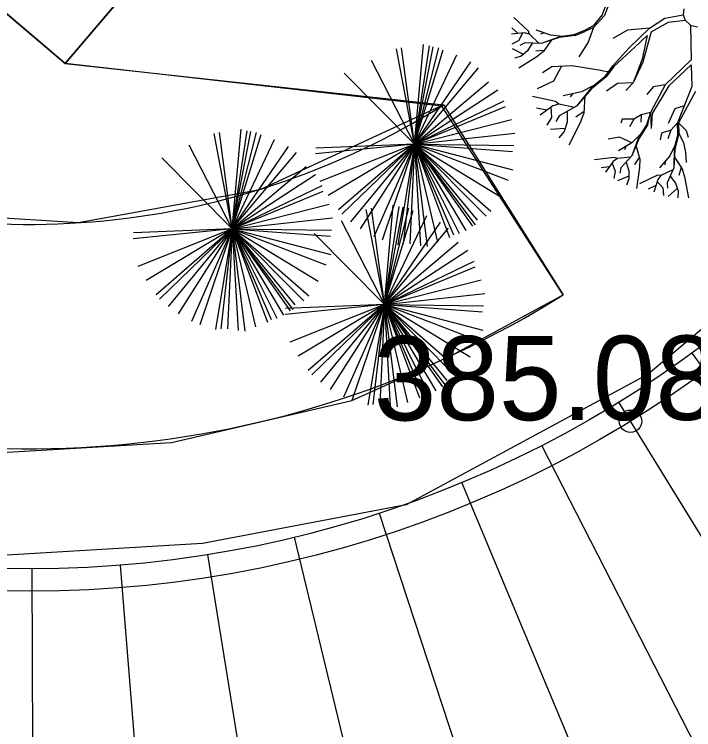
# Model space of a CAD drawing. Extents: x -438303 to -437792, y -1133191 to -1132731.
# Drawn here: x -438058.05 to -438052, y -1132962.9 to -1132956.53 of the extents above; entities that cross this region are included whole.
import ezdxf

# ---------------------------------------------------------------- set-up
doc = ezdxf.new("R2010")
doc.units = 0
for name, color, linetype in [('NADPRAZI', 7, 'Continuous'), ('OSY', 7, 'Continuous'), ('SILNA 1', 7, 'Continuous'), ('Vrstva 1', 7, 'Continuous'), ('Vrstva 3', 7, 'Continuous'), ('Vrstva 40', 7, 'Continuous')]:
    doc.layers.add(name, color=color, linetype=linetype)

# ---------------------------------------------------------------- blocks, each defined once
blk = doc.blocks.new('A$C6C6266F8')
at = {"layer": 'OSY'}
for p, q in [((38.268, -92.388), (74.623, -180.157)), ((60.258, -185.456), (30.902, -95.106)), ((-45.522, -189.612), (-23.345, -97.237)), ((45.522, -189.612), (23.345, -97.237)), ((-30.505, -192.599), (-15.643, -98.769)), ((30.505, -192.599), (15.643, -98.769)), ((-15.3, -194.399), (-7.846, -99.692)), ((0, -195), (0, -100)), ((7.846, -99.692), (15.3, -194.399))]:
    blk.add_line(p, q, dxfattribs=at)

msp = doc.modelspace()

# ---------------------------------------------------------------- linework, layer by layer
at = {"layer": 'DEFPOINTS'}
msp.add_circle((-438057.9113, -1132951.4681), 10.2, dxfattribs=at)
msp.add_circle((-438057.9113, -1132951.4681), 10.2, dxfattribs=at)
at = {"layer": 'NADPRAZI'}
msp.add_circle((-438057.9113, -1132951.4681), 10, dxfattribs=at)
msp.add_circle((-438057.9113, -1132951.4681), 10, dxfattribs=at)
msp.add_circle((-438057.9113, -1132951.4681), 10, dxfattribs=at)
msp.add_circle((-438057.9113, -1132951.4681), 10, dxfattribs=at)
msp.add_circle((-438057.9113, -1132951.4681), 10, dxfattribs=at)
at = {"layer": 'SILNA 1'}
msp.add_circle((-438052.5625, -1132960.1531), 0.1, dxfattribs=at)
msp.add_circle((-438052.5625, -1132960.1531), 0.1, dxfattribs=at)
msp.add_circle((-438052.5625, -1132960.1531), 0.1, dxfattribs=at)
msp.add_circle((-438052.5625, -1132960.1531), 0.1, dxfattribs=at)
at = {"layer": 'Vrstva 1'}
for p, q in [((-438052.4146, -1132950.8696), (-438057.5966, -1132956.9644)), ((-438057.5966, -1132956.9644), (-438063.6914, -1132951.7824)), ((-438052.7262, -1132956.3612), (-438052.7949, -1132956.5367)), ((-438052.7595, -1132956.3777), (-438052.8134, -1132956.5318)), ((-438052.0875, -1132956.4789), (-438052.0924, -1132956.5311)), ((-438053.4718, -1132956.676), (-438053.6008, -1132956.5553)), ((-438052.8134, -1132956.5318), (-438052.8958, -1132956.6303)), ((-438052.7949, -1132956.5367), (-438052.8915, -1132956.6429)), ((-438052.3944, -1132956.6509), (-438052.2565, -1132956.5601)), ((-438052.2565, -1132956.5601), (-438052.0924, -1132956.5311)), ((-438052.0924, -1132956.5311), (-438052.0764, -1132956.578)), ((-438052.3781, -1132956.6813), (-438052.2237, -1132956.5977)), ((-438052.2237, -1132956.5977), (-438052.0764, -1132956.578)), ((-438052.0764, -1132956.578), (-438052.0288, -1132956.6232)), ((-438052.0288, -1132956.6232), (-438052.0213, -1132956.933)), ((-438052.0288, -1132956.6232), (-438051.9657, -1132956.6376)), ((-438053.5626, -1132956.6973), (-438053.6182, -1132956.6459)), ((-438053.4618, -1132956.7044), (-438053.4718, -1132956.676)), ((-438053.2705, -1132956.7136), (-438053.4028, -1132956.6679)), ((-438052.9724, -1132956.6698), (-438053.0654, -1132956.7093)), ((-438053.0558, -1132956.7159), (-438052.9687, -1132956.6787)), ((-438052.8958, -1132956.6303), (-438052.9724, -1132956.6698)), ((-438052.8915, -1132956.6429), (-438052.9687, -1132956.6787)), ((-438052.8915, -1132956.6429), (-438052.9398, -1132956.7748)), ((-438052.5899, -1132956.6665), (-438052.7199, -1132956.7427)), ((-438052.3944, -1132956.6509), (-438052.5899, -1132956.6665)), ((-438052.5731, -1132956.826), (-438052.3944, -1132956.6509)), ((-438052.3781, -1132956.6813), (-438052.451, -1132956.9539)), ((-438053.5054, -1132956.6919), (-438053.6227, -1132956.703)), ((-438053.5239, -1132956.6949), (-438053.5591, -1132956.7623)), ((-438053.4618, -1132956.7044), (-438053.5054, -1132956.6919)), ((-438053.3761, -1132956.7861), (-438053.4618, -1132956.7044)), ((-438053.3314, -1132956.6929), (-438053.3624, -1132956.7022)), ((-438053.1909, -1132956.726), (-438053.3586, -1132956.7868)), ((-438053.1975, -1132956.7343), (-438053.3586, -1132956.7868)), ((-438053.2642, -1132956.7526), (-438053.337, -1132956.8594)), ((-438053.1675, -1132956.723), (-438053.2705, -1132956.7136)), ((-438053.0558, -1132956.7159), (-438053.1975, -1132956.7343)), ((-438053.0654, -1132956.7093), (-438053.1909, -1132956.726)), ((-438052.5242, -1132956.8179), (-438052.4141, -1132956.715)), ((-438052.4141, -1132956.715), (-438052.457, -1132956.9268)), ((-438054.4854, -1132957.6831), (-438054.4067, -1132956.7962)), ((-438054.4854, -1132957.6831), (-438054.3531, -1132956.8089)), ((-438054.4854, -1132957.6831), (-438054.3197, -1132956.8153)), ((-438053.5591, -1132956.7623), (-438053.6185, -1132956.7938)), ((-438053.5039, -1132956.7817), (-438053.5465, -1132956.8039)), ((-438053.3586, -1132956.7868), (-438053.5039, -1132956.7817)), ((-438053.4366, -1132956.7843), (-438053.4794, -1132956.8524)), ((-438052.9398, -1132956.7748), (-438053.0231, -1132956.9054)), ((-438052.7112, -1132956.9927), (-438052.5242, -1132956.8179)), ((-438054.4854, -1132957.6831), (-438054.6474, -1132956.835)), ((-438054.4854, -1132957.6831), (-438054.6005, -1132956.8254)), ((-438054.4854, -1132957.6831), (-438054.2694, -1132956.8248)), ((-438054.4854, -1132957.6831), (-438054.2293, -1132956.8438)), ((-438053.5153, -1132956.8835), (-438053.6129, -1132956.8341)), ((-438053.4794, -1132956.8524), (-438053.5345, -1132956.8994)), ((-438053.3294, -1132956.8485), (-438053.4041, -1132956.8546)), ((-438053.337, -1132956.8594), (-438053.3974, -1132956.9061)), ((-438052.7204, -1132956.9858), (-438052.5731, -1132956.826)), ((-438054.4854, -1132957.6831), (-438054.8681, -1132956.9379)), ((-438054.4854, -1132957.6831), (-438054.1088, -1132956.8884)), ((-438053.5345, -1132956.8994), (-438053.5916, -1132956.9186)), ((-438053.3974, -1132956.9061), (-438053.5561, -1132957.0061)), ((-438052.457, -1132956.9268), (-438052.5398, -1132957.136)), ((-438052.0213, -1132956.933), (-438052.2527, -1132957.155)), ((-438054.4854, -1132957.6831), (-438053.9848, -1132956.9491)), ((-438054.4854, -1132957.6831), (-438053.9146, -1132957.0034)), ((-438053.2641, -1132956.9937), (-438053.3456, -1132957.0467)), ((-438053.0854, -1132956.9858), (-438053.2641, -1132956.9937)), ((-438053.1772, -1132956.9899), (-438053.248, -1132957.1221)), ((-438052.8089, -1132957.0308), (-438053.0854, -1132956.9858)), ((-438052.7916, -1132957.0843), (-438052.7204, -1132956.9858)), ((-438052.7112, -1132956.9927), (-438052.7777, -1132957.0846)), ((-438052.451, -1132956.9539), (-438052.5398, -1132957.136)), ((-438052.0205, -1132956.9759), (-438052.2217, -1132957.1652)), ((-438052.0205, -1132956.9759), (-438052.0152, -1132957.1711)), ((-438054.4854, -1132957.6831), (-438055.112, -1132957.0504)), ((-438052.8089, -1132957.0308), (-438052.757, -1132957.0367)), ((-438054.4854, -1132957.6831), (-438053.8274, -1132957.128)), ((-438053.248, -1132957.1221), (-438053.3942, -1132957.1908)), ((-438052.7777, -1132957.0846), (-438052.9113, -1132957.1922)), ((-438052.7916, -1132957.0843), (-438052.91, -1132957.1797)), ((-438052.5398, -1132957.136), (-438052.6782, -1132957.1442)), ((-438052.5398, -1132957.136), (-438052.6051, -1132957.2042)), ((-438054.4854, -1132957.6831), (-438053.7436, -1132957.1984)), ((-438052.91, -1132957.1797), (-438053.0435, -1132957.346)), ((-438052.9113, -1132957.1922), (-438053.0435, -1132957.346)), ((-438052.8879, -1132957.1618), (-438052.9994, -1132957.2165)), ((-438052.6782, -1132957.1442), (-438052.7758, -1132957.2124)), ((-438052.3591, -1132957.1714), (-438052.4164, -1132957.2399)), ((-438052.2527, -1132957.155), (-438052.3851, -1132957.4023)), ((-438052.2217, -1132957.1652), (-438052.3702, -1132957.4119)), ((-438052.2527, -1132957.155), (-438052.3591, -1132957.1714)), ((-438052.0152, -1132957.1711), (-438052.1435, -1132957.4944)), ((-438053.2292, -1132957.3028), (-438053.436, -1132957.2596)), ((-438052.9994, -1132957.2165), (-438053.1632, -1132957.2521)), ((-438053.0744, -1132957.2325), (-438053.1008, -1132957.2613)), ((-438052.9687, -1132957.2521), (-438052.977, -1132957.4067)), ((-438051.9834, -1132957.2146), (-438052.1339, -1132957.494)), ((-438054.4854, -1132957.6831), (-438053.6865, -1132957.2975)), ((-438053.2011, -1132957.3259), (-438053.2536, -1132957.3408)), ((-438053.2011, -1132957.3259), (-438053.2292, -1132957.3028)), ((-438053.062, -1132957.356), (-438053.2011, -1132957.3259)), ((-438054.4854, -1132957.6831), (-438053.6765, -1132957.3486)), ((-438053.3086, -1132957.3812), (-438053.3979, -1132957.3635)), ((-438053.2536, -1132957.3408), (-438053.367, -1132957.4246)), ((-438053.2707, -1132957.3547), (-438053.2649, -1132957.4459)), ((-438053.0435, -1132957.346), (-438053.1962, -1132957.4315)), ((-438053.1256, -1132957.3918), (-438053.1268, -1132957.4886)), ((-438052.9757, -1132957.3912), (-438053.0486, -1132957.4438)), ((-438052.1665, -1132957.3686), (-438052.2257, -1132957.5005)), ((-438052.083, -1132957.3413), (-438052.1665, -1132957.3686)), ((-438053.2649, -1132957.4459), (-438053.3064, -1132957.5153)), ((-438053.1962, -1132957.4315), (-438053.2259, -1132957.4805)), ((-438052.977, -1132957.4067), (-438053.0092, -1132957.4926)), ((-438052.467, -1132957.4233), (-438052.5323, -1132957.4601)), ((-438052.467, -1132957.4233), (-438052.4692, -1132957.4864)), ((-438052.3851, -1132957.4023), (-438052.467, -1132957.4233)), ((-438052.3851, -1132957.4023), (-438052.4202, -1132957.5124)), ((-438052.409, -1132957.5091), (-438052.3851, -1132957.4023)), ((-438052.3851, -1132957.4023), (-438052.3772, -1132957.545)), ((-438052.3702, -1132957.4119), (-438052.3772, -1132957.545)), ((-438054.4854, -1132957.6831), (-438053.6227, -1132957.4638)), ((-438053.1268, -1132957.4886), (-438053.1537, -1132957.5712)), ((-438053.0092, -1132957.4926), (-438053.1102, -1132957.694)), ((-438052.636, -1132957.4606), (-438052.6495, -1132957.4973)), ((-438052.5323, -1132957.4601), (-438052.636, -1132957.4606)), ((-438052.5323, -1132957.4601), (-438052.5711, -1132957.5285)), ((-438052.4202, -1132957.5124), (-438052.4884, -1132957.6192)), ((-438052.409, -1132957.5091), (-438052.4857, -1132957.6291)), ((-438052.1435, -1132957.4944), (-438052.2038, -1132957.5589)), ((-438052.1413, -1132957.5954), (-438052.1435, -1132957.4944)), ((-438052.1339, -1132957.494), (-438052.0657, -1132957.5633)), ((-438052.1339, -1132957.494), (-438052.1317, -1132957.5885)), ((-438056.1081, -1132958.4382), (-438056.2232, -1132957.5806)), ((-438056.1081, -1132958.4382), (-438056.0294, -1132957.5514)), ((-438056.1081, -1132958.4382), (-438055.9758, -1132957.564)), ((-438056.1081, -1132958.4382), (-438055.9424, -1132957.5704)), ((-438056.1081, -1132958.4382), (-438055.8921, -1132957.58)), ((-438053.1445, -1132957.5431), (-438053.275, -1132957.5529)), ((-438053.1537, -1132957.5712), (-438053.2008, -1132957.6268)), ((-438052.2038, -1132957.5589), (-438052.2853, -1132957.5868)), ((-438052.2038, -1132957.5589), (-438052.2311, -1132957.6372)), ((-438052.0657, -1132957.5633), (-438052.0498, -1132957.6224)), ((-438056.1081, -1132958.4382), (-438056.2701, -1132957.5901)), ((-438056.1081, -1132958.4382), (-438055.852, -1132957.599)), ((-438056.1081, -1132958.4382), (-438055.7315, -1132957.6436)), ((-438054.4854, -1132957.6831), (-438053.5924, -1132957.5854)), ((-438052.6608, -1132957.6218), (-438052.7619, -1132957.6398)), ((-438052.5491, -1132957.6721), (-438052.6608, -1132957.6218)), ((-438052.4884, -1132957.6192), (-438052.5492, -1132957.7864)), ((-438052.4857, -1132957.6291), (-438052.5492, -1132957.7864)), ((-438052.4756, -1132957.5987), (-438052.5491, -1132957.6721)), ((-438052.2853, -1132957.5868), (-438052.2984, -1132957.6443)), ((-438052.1413, -1132957.5954), (-438052.1725, -1132957.718)), ((-438052.1317, -1132957.5885), (-438052.1668, -1132957.7269)), ((-438052.1317, -1132957.5885), (-438052.0903, -1132957.6703)), ((-438056.1081, -1132958.4382), (-438056.4908, -1132957.6931)), ((-438056.1081, -1132958.4382), (-438055.6075, -1132957.7042)), ((-438054.4854, -1132957.6831), (-438055.3683, -1132957.7711)), ((-438054.4854, -1132957.6831), (-438055.3651, -1132957.7198)), ((-438054.4854, -1132957.6831), (-438055.3276, -1132958.0175)), ((-438054.4854, -1132957.6831), (-438055.2539, -1132958.1423)), ((-438054.4854, -1132957.6831), (-438055.1633, -1132958.27)), ((-438054.4854, -1132957.6831), (-438055.1332, -1132958.3085)), ((-438054.4854, -1132957.6831), (-438055.056, -1132958.3755)), ((-438054.4854, -1132957.6831), (-438054.969, -1132958.4394)), ((-438054.4854, -1132957.6831), (-438054.8484, -1132958.5096)), ((-438054.4854, -1132957.6831), (-438054.7747, -1132958.5383)), ((-438054.4854, -1132957.6831), (-438054.6343, -1132958.5795)), ((-438054.4854, -1132957.6831), (-438054.5874, -1132958.5731)), ((-438054.4854, -1132957.6831), (-438054.5272, -1132958.573)), ((-438054.4854, -1132957.6831), (-438053.6086, -1132957.912)), ((-438054.4854, -1132957.6831), (-438053.8051, -1132958.2803)), ((-438054.4854, -1132957.6831), (-438053.9689, -1132958.4152)), ((-438054.4854, -1132957.6831), (-438054.3733, -1132958.5951)), ((-438054.4854, -1132957.6831), (-438054.4335, -1132958.5888)), ((-438054.4854, -1132957.6831), (-438054.2798, -1132958.5565)), ((-438054.4854, -1132957.6831), (-438054.1727, -1132958.5148)), ((-438054.4854, -1132957.6831), (-438054.1394, -1132958.4923)), ((-438054.4854, -1132957.6831), (-438054.0892, -1132958.4793)), ((-438054.4854, -1132957.6831), (-438054.029, -1132958.4536)), ((-438054.4854, -1132957.6831), (-438053.9454, -1132958.4022)), ((-438054.4854, -1132957.6831), (-438053.9289, -1132958.3607)), ((-438054.4854, -1132957.6831), (-438053.8486, -1132958.3252)), ((-438054.4854, -1132957.6831), (-438053.6518, -1132958.0048)), ((-438054.4854, -1132957.6831), (-438053.7217, -1132958.1489)), ((-438054.4854, -1132957.6831), (-438053.6122, -1132957.7487)), ((-438054.4854, -1132957.6831), (-438053.6022, -1132957.6942)), ((-438052.5491, -1132957.6721), (-438052.6688, -1132957.7437)), ((-438052.6038, -1132957.7046), (-438052.617, -1132957.7344)), ((-438052.515, -1132957.6922), (-438052.4804, -1132957.816)), ((-438052.1665, -1132957.6952), (-438052.2133, -1132957.7878)), ((-438052.0903, -1132957.6703), (-438052.0736, -1132957.7582)), ((-438056.1081, -1132958.4382), (-438055.5372, -1132957.7585)), ((-438052.1725, -1132957.718), (-438052.1777, -1132957.8961)), ((-438052.1668, -1132957.7269), (-438052.1777, -1132957.8961)), ((-438052.0736, -1132957.7582), (-438052.0665, -1132957.8457)), ((-438056.1081, -1132958.4382), (-438056.7347, -1132957.8055)), ((-438052.7074, -1132957.8013), (-438052.8821, -1132957.8227)), ((-438052.7166, -1132957.8376), (-438052.7834, -1132957.9345)), ((-438052.679, -1132957.8121), (-438052.7166, -1132957.8376)), ((-438052.679, -1132957.8121), (-438052.7074, -1132957.8013)), ((-438052.5611, -1132957.799), (-438052.679, -1132957.8121)), ((-438052.5492, -1132957.7864), (-438052.6471, -1132957.8943)), ((-438052.4838, -1132957.8038), (-438052.5273, -1132957.8647)), ((-438052.4804, -1132957.816), (-438052.4829, -1132957.8927)), ((-438052.2133, -1132957.7878), (-438052.3046, -1132957.8933)), ((-438052.2548, -1132957.8361), (-438052.2577, -1132957.8685)), ((-438052.1746, -1132957.796), (-438052.1028, -1132957.9029)), ((-438056.1081, -1132958.4382), (-438055.45, -1132957.8832)), ((-438054.465, -1132957.8526), (-438054.465, -1132957.8559)), ((-438052.7492, -1132957.8846), (-438052.8245, -1132957.8939)), ((-438052.7265, -1132957.8535), (-438052.6973, -1132957.9241)), ((-438052.6471, -1132957.8943), (-438052.6573, -1132957.9409)), ((-438052.6016, -1132957.844), (-438052.577, -1132957.9209)), ((-438052.4829, -1132957.8927), (-438052.509, -1132958.0787)), ((-438052.1777, -1132957.8961), (-438052.2363, -1132958.0296)), ((-438052.11, -1132957.892), (-438052.1317, -1132957.9637)), ((-438056.1081, -1132958.4382), (-438055.3663, -1132957.9535)), ((-438052.6973, -1132957.9241), (-438052.7117, -1132957.9899)), ((-438052.577, -1132957.9209), (-438052.5762, -1132957.9932)), ((-438052.3226, -1132957.9604), (-438052.4824, -1132958.036)), ((-438052.2926, -1132957.9617), (-438052.3226, -1132957.9604)), ((-438052.2926, -1132957.9617), (-438052.3199, -1132957.9977)), ((-438052.1847, -1132957.9119), (-438052.2926, -1132957.9617)), ((-438052.1028, -1132957.9029), (-438052.0811, -1132957.9758)), ((-438052.5763, -1132957.9685), (-438052.6769, -1132958.0116)), ((-438052.5762, -1132957.9932), (-438052.5989, -1132958.0494)), ((-438052.3199, -1132957.9977), (-438052.3531, -1132958.1104)), ((-438052.3242, -1132958.0156), (-438052.2745, -1132958.074)), ((-438052.209, -1132957.9678), (-438052.1613, -1132958.0325)), ((-438052.0811, -1132957.9758), (-438052.0471, -1132958.1607)), ((-438056.1081, -1132958.4382), (-438055.3092, -1132958.0526)), ((-438052.336, -1132958.0526), (-438052.4046, -1132958.0854)), ((-438052.2745, -1132958.074), (-438052.2675, -1132958.1403)), ((-438052.2363, -1132958.0296), (-438052.2313, -1132958.0772)), ((-438052.146, -1132958.0777), (-438052.2275, -1132958.1498)), ((-438052.1613, -1132958.0325), (-438052.1381, -1132958.1008)), ((-438056.1081, -1132958.4382), (-438055.2991, -1132958.1037)), ((-438052.1381, -1132958.1008), (-438052.1413, -1132958.1616)), ((-438056.1081, -1132958.4382), (-438055.2454, -1132958.219)), ((-438054.7535, -1132959.1127), (-438054.9155, -1132958.2646)), ((-438054.7535, -1132959.1127), (-438054.8686, -1132958.2551)), ((-438054.7535, -1132959.1127), (-438054.6748, -1132958.2259)), ((-438054.7535, -1132959.1127), (-438054.6212, -1132958.2386)), ((-438054.7535, -1132959.1127), (-438054.5878, -1132958.245)), ((-438054.7535, -1132959.1127), (-438054.5375, -1132958.2545)), ((-438054.7535, -1132959.1127), (-438054.4974, -1132958.2735)), ((-438056.1081, -1132958.4382), (-438055.2151, -1132958.3405)), ((-438054.7535, -1132959.1127), (-438054.3769, -1132958.3181)), ((-438054.7535, -1132959.1127), (-438055.1362, -1132958.3676)), ((-438054.7535, -1132959.1127), (-438054.2529, -1132958.3788)), ((-438056.1081, -1132958.4382), (-438056.991, -1132958.5263)), ((-438056.1081, -1132958.4382), (-438056.9877, -1132958.475)), ((-438056.1081, -1132958.4382), (-438056.9503, -1132958.7726)), ((-438056.1081, -1132958.4382), (-438056.8766, -1132958.8974)), ((-438056.1081, -1132958.4382), (-438056.786, -1132959.0252)), ((-438056.1081, -1132958.4382), (-438056.7559, -1132959.0636)), ((-438056.1081, -1132958.4382), (-438056.6787, -1132959.1307)), ((-438056.1081, -1132958.4382), (-438056.5916, -1132959.1946)), ((-438056.1081, -1132958.4382), (-438056.4711, -1132959.2647)), ((-438056.1081, -1132958.4382), (-438056.3974, -1132959.2935)), ((-438056.1081, -1132958.4382), (-438056.257, -1132959.3347)), ((-438056.1081, -1132958.4382), (-438056.2101, -1132959.3283)), ((-438056.1081, -1132958.4382), (-438056.1499, -1132959.3282)), ((-438056.1081, -1132958.4382), (-438055.2313, -1132958.6671)), ((-438056.1081, -1132958.4382), (-438055.4278, -1132959.0355)), ((-438056.1081, -1132958.4382), (-438055.5916, -1132959.1704)), ((-438056.1081, -1132958.4382), (-438055.996, -1132959.3503)), ((-438056.1081, -1132958.4382), (-438056.0562, -1132959.3439)), ((-438056.1081, -1132958.4382), (-438055.9024, -1132959.3116)), ((-438056.1081, -1132958.4382), (-438055.7954, -1132959.27)), ((-438056.1081, -1132958.4382), (-438055.762, -1132959.2475)), ((-438056.1081, -1132958.4382), (-438055.7118, -1132959.2345)), ((-438056.1081, -1132958.4382), (-438055.6517, -1132959.2088)), ((-438056.1081, -1132958.4382), (-438055.5681, -1132959.1574)), ((-438056.1081, -1132958.4382), (-438055.5516, -1132959.1159)), ((-438056.1081, -1132958.4382), (-438055.4713, -1132959.0804)), ((-438056.1081, -1132958.4382), (-438055.2745, -1132958.7599)), ((-438056.1081, -1132958.4382), (-438055.3444, -1132958.9041)), ((-438056.1081, -1132958.4382), (-438055.2349, -1132958.5038)), ((-438056.1081, -1132958.4382), (-438055.2248, -1132958.4494)), ((-438054.7535, -1132959.1127), (-438054.1826, -1132958.4331)), ((-438054.7535, -1132959.1127), (-438055.3801, -1132958.48)), ((-438054.7535, -1132959.1127), (-438054.0954, -1132958.5577)), ((-438056.0877, -1132958.6078), (-438056.0876, -1132958.6111)), ((-438054.7535, -1132959.1127), (-438054.0117, -1132958.628)), ((-438054.7535, -1132959.1127), (-438053.9546, -1132958.7272)), ((-438054.7535, -1132959.1127), (-438053.9445, -1132958.7782)), ((-438054.7535, -1132959.1127), (-438053.8908, -1132958.8935)), ((-438054.7535, -1132959.1127), (-438053.8605, -1132959.015)), ((-438054.7535, -1132959.1127), (-438055.6364, -1132959.2008)), ((-438054.7535, -1132959.1127), (-438055.6331, -1132959.1495)), ((-438054.7535, -1132959.1127), (-438055.5957, -1132959.4471)), ((-438054.7535, -1132959.1127), (-438055.5219, -1132959.5719)), ((-438054.7535, -1132959.1127), (-438055.4314, -1132959.6997)), ((-438054.7535, -1132959.1127), (-438055.4012, -1132959.7381)), ((-438054.7535, -1132959.1127), (-438055.3241, -1132959.8052)), ((-438054.7535, -1132959.1127), (-438055.237, -1132959.8691)), ((-438054.7535, -1132959.1127), (-438055.1165, -1132959.9392)), ((-438054.7535, -1132959.1127), (-438055.0428, -1132959.968)), ((-438054.7535, -1132959.1127), (-438054.9024, -1132960.0092)), ((-438054.7535, -1132959.1127), (-438054.8555, -1132960.0028)), ((-438054.7535, -1132959.1127), (-438054.7953, -1132960.0027)), ((-438054.7535, -1132959.1127), (-438053.8767, -1132959.3416)), ((-438054.7535, -1132959.1127), (-438054.0732, -1132959.71)), ((-438054.7535, -1132959.1127), (-438054.2369, -1132959.8449)), ((-438054.7535, -1132959.1127), (-438054.6414, -1132960.0248)), ((-438054.7535, -1132959.1127), (-438054.7016, -1132960.0185)), ((-438054.7535, -1132959.1127), (-438054.5478, -1132959.9861)), ((-438054.7535, -1132959.1127), (-438054.4408, -1132959.9445)), ((-438054.7535, -1132959.1127), (-438054.4074, -1132959.922)), ((-438054.7535, -1132959.1127), (-438054.3572, -1132959.909)), ((-438054.7535, -1132959.1127), (-438054.2971, -1132959.8833)), ((-438054.7535, -1132959.1127), (-438054.2135, -1132959.8319)), ((-438054.7535, -1132959.1127), (-438054.197, -1132959.7904)), ((-438054.7535, -1132959.1127), (-438054.1167, -1132959.7549)), ((-438054.7535, -1132959.1127), (-438053.9199, -1132959.4345)), ((-438054.7535, -1132959.1127), (-438053.9898, -1132959.5786)), ((-438054.7535, -1132959.1127), (-438053.8803, -1132959.1784)), ((-438054.7535, -1132959.1127), (-438053.8702, -1132959.1239)), ((-438054.733, -1132959.2823), (-438054.733, -1132959.2856)), ((-438052.3488, -1132960.141), (-438052.3488, -1132960.141))]:
    msp.add_line(p, q, dxfattribs=at)
for points in [[(-438063.6914, -1132951.7824), (-438057.5966, -1132956.9644), (-438054.2272, -1132957.3337), (-438055.8623, -1132958.0906), (-438057.4772, -1132958.3859), (-438059.196, -1132958.2772), (-438060.6078, -1132957.8581), (-438061.3816, -1132959.7024), (-438059.9339, -1132960.1842), (-438058.2128, -1132960.4347), (-438056.649, -1132960.3416), (-438055.0428, -1132959.968), (-438054.1613, -1132959.5701), (-438053.1627, -1132959.0269), (-438054.2427, -1132957.3437), (-438057.5966, -1132956.9644), (-438052.4146, -1132950.8696)], [(-438048.4027, -1132954.4312), (-438049.5929, -1132957.0177), (-438050.801, -1132958.389), (-438052.4038, -1132959.7345), (-438054.5595, -1132960.8969), (-438056.3747, -1132961.2424), (-438058.6639, -1132961.3782), (-438061.0858, -1132960.935), (-438063.4563, -1132959.781), (-438065.565, -1132957.8629), (-438067.0957, -1132955.4436)]]:
    msp.add_lwpolyline(points, dxfattribs=at)
at = {"layer": 'Vrstva 40'}
msp.add_line((-438054.2272, -1132957.3337), (-438053.1627, -1132959.0269), dxfattribs=at)
for radius in [6.9418, 8.9418]:
    msp.add_arc((-438057.9221, -1132951.4569), radius, 247.23888, 302.15824, dxfattribs=at)

# ---------------------------------------------------------------- block references
at = {"layer": 'OSY', "xscale": 0.10000000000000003, "yscale": 0.10000000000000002, "rotation": 13.627557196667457}
msp.add_blockref('A$C6C6266F8', (-438057.9113, -1132951.4681), dxfattribs=at)

# ---------------------------------------------------------------- texts
at = {"layer": 'Vrstva 3'}
msp.add_text('385.08 ', height=0.75, rotation=0.10417, dxfattribs=at).set_placement((-438054.8488, -1132960.1455))

doc.saveas('drawing.dxf')
